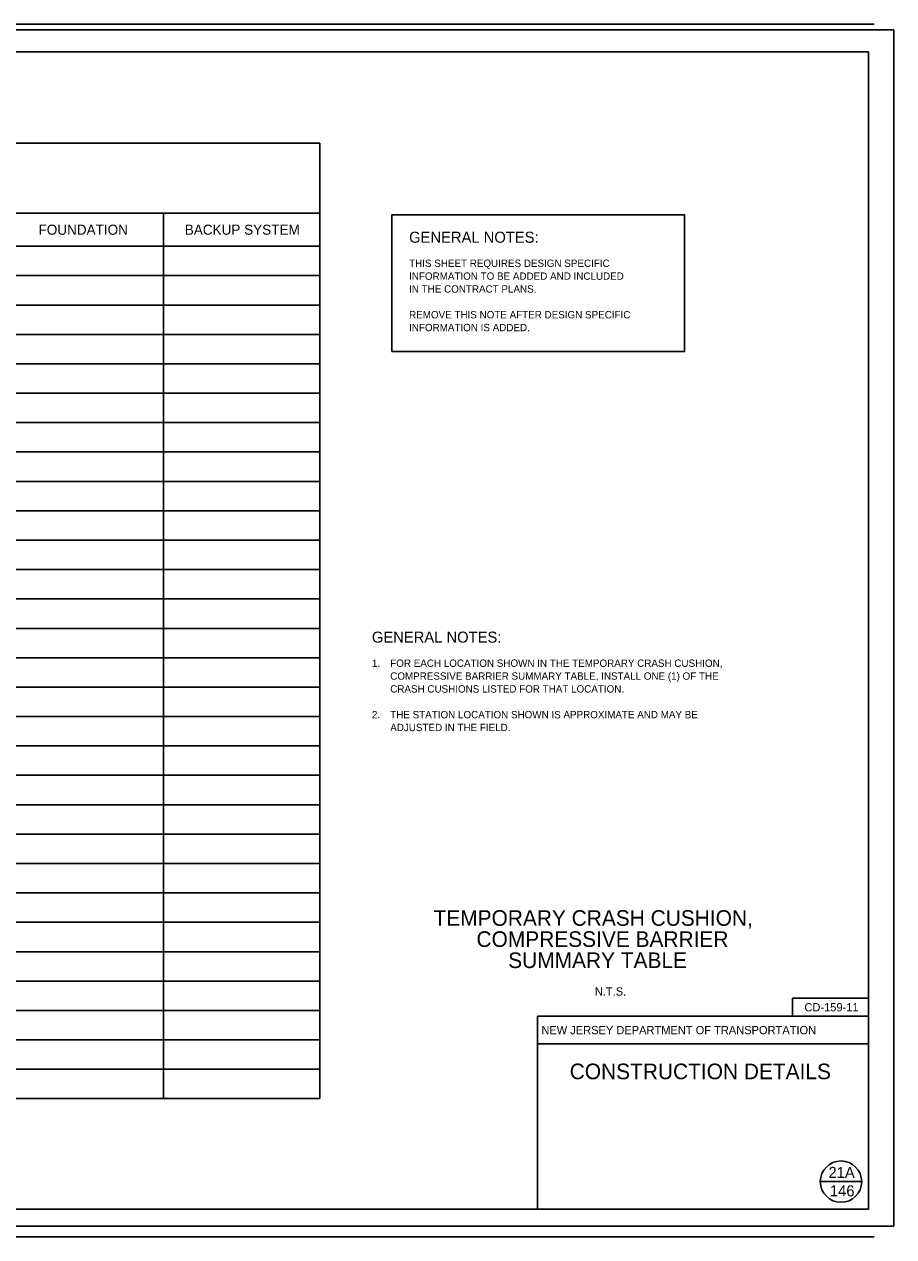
# Model space of a CAD drawing. Extents: x 465470 to 466531, y 459205 to 459865.
# Drawn here: x 466058 to 466531, y 459205 to 459865 of the extents above; entities that cross this region are included whole.
import ezdxf

# ---------------------------------------------------------------- set-up
doc = ezdxf.new("R2010")
doc.units = 0
for name, color, linetype in [('1', 7, 'Continuous'), ('41', 7, 'Continuous'), ('5', 7, 'Continuous'), ('63', 7, 'Continuous')]:
    doc.layers.add(name, color=color, linetype=linetype)

msp = doc.modelspace()

# ---------------------------------------------------------------- linework, layer by layer
at = {"layer": '1'}
for p, q in [((466520.35, 459865.34), (465472.17, 459865.34)), ((466517.35, 459850.34), (465527.35, 459850.34)), ((466517.35, 459220.34), (466517.35, 459850.34)), ((465558.8, 459800.64), (466218.8, 459800.64)), ((466218.8, 459280.52), (466218.8, 459800.64)), ((465558.8, 459762.52), (466218.8, 459762.52)), ((466133.8, 459280.52), (466133.8, 459762.52)), ((465558.8, 459744.52), (466218.8, 459744.52)), ((465558.8, 459728.52), (466218.8, 459728.52)), ((465558.8, 459712.52), (466218.8, 459712.52)), ((465558.8, 459696.52), (466218.8, 459696.52)), ((465558.8, 459680.52), (466218.8, 459680.52)), ((465558.8, 459664.52), (466218.8, 459664.52)), ((465558.8, 459648.52), (466218.8, 459648.52)), ((465558.8, 459632.52), (466218.8, 459632.52)), ((465558.8, 459616.52), (466218.8, 459616.52)), ((465558.8, 459600.52), (466218.8, 459600.52)), ((465558.8, 459584.52), (466218.8, 459584.52)), ((465558.8, 459568.52), (466218.8, 459568.52)), ((465558.8, 459552.52), (466218.8, 459552.52)), ((465558.8, 459536.52), (466218.8, 459536.52)), ((465558.8, 459520.52), (466218.8, 459520.52)), ((465558.8, 459504.52), (466218.8, 459504.52)), ((465558.8, 459488.52), (466218.8, 459488.52)), ((465558.8, 459472.52), (466218.8, 459472.52)), ((465558.8, 459456.52), (466218.8, 459456.52)), ((465558.8, 459440.52), (466218.8, 459440.52)), ((465558.8, 459424.52), (466218.8, 459424.52)), ((465558.8, 459408.52), (466218.8, 459408.52)), ((465558.8, 459392.52), (466218.8, 459392.52)), ((465558.8, 459376.52), (466218.8, 459376.52)), ((465558.8, 459360.52), (466218.8, 459360.52)), ((465558.8, 459344.52), (466218.8, 459344.52)), ((466517.35, 459335.19), (466476.01, 459335.19)), ((466476.01, 459335.19), (466476.01, 459325.34)), ((465558.8, 459328.52), (466218.8, 459328.52)), ((466517.35, 459325.34), (466337.35, 459325.34)), ((466337.35, 459325.34), (466337.35, 459220.34)), ((465558.8, 459312.52), (466218.8, 459312.52)), ((466517.35, 459310.34), (466337.35, 459310.34)), ((465558.8, 459296.52), (466218.8, 459296.52)), ((465558.8, 459280.52), (466218.8, 459280.52)), ((466502.35, 459235.34), (466491.1, 459235.34)), ((466502.35, 459235.34), (466513.6, 459235.34)), ((465527.35, 459220.34), (466517.35, 459220.34)), ((466520.35, 459205.34), (465472.17, 459205.34))]:
    msp.add_line(p, q, dxfattribs=at)
msp.add_lwpolyline([(466258.02, 459687.2), (466417.29, 459687.2), (466417.29, 459761.57), (466258.02, 459761.57)], close=True, dxfattribs=at)
msp.add_circle((466502.35, 459235.34), 11.25, dxfattribs=at)
at = {"layer": '41'}
msp.add_line((466496.68, 459330.27), (466496.68, 459330.27), dxfattribs=at)
msp.add_lwpolyline([(465469.62, 459211.1), (466531.03, 459211.1), (466531.03, 459862.3), (465469.62, 459862.3)], close=True, dxfattribs=at)

# ---------------------------------------------------------------- texts
at = {"layer": '1'}
for s, height, p in [('THIS SHEET REQUIRES DESIGN SPECIFIC', 4, (466267.43, 459733.25)), ('INFORMATION TO BE ADDED AND INCLUDED', 4, (466267.43, 459726.25)), ('IN THE CONTRACT PLANS. ', 4, (466267.43, 459719.25)), ('REMOVE THIS NOTE AFTER DESIGN SPECIFIC', 4, (466267.43, 459705.25)), ('INFORMATION IS ADDED.', 4, (466267.43, 459698.25)), ('TEMPORARY CRASH CUSHION,', 8.5, (466280.71, 459374.61)), ('COMPRESSIVE BARRIER', 8.5, (466304.08, 459363.11)), ('SUMMARY TABLE', 8.5, (466321.33, 459351.61)), ('CD-159-11', 4.5, (466482.46, 459328.02)), ('NEW JERSEY DEPARTMENT OF TRANSPORTATION', 4.5, (466339.37, 459315.59)), ('CONSTRUCTION DETAILS', 8.5, (466354.79, 459291.09)), ('146', 6, (466496.32, 459227.34))]:
    msp.add_text(s, height=height, dxfattribs=at).set_placement(p)
at = {"layer": '5'}
for s, height, p in [('FOUNDATION', 5.5, (466065.86, 459750.77)), ('BACKUP SYSTEM', 5.5, (466145.42, 459750.77)), ('GENERAL NOTES:', 6, (466267.43, 459746.42)), ('GENERAL NOTES:', 6, (466247.19, 459528.73)), ('1.', 4, (466247.19, 459515.55)), ('FOR EACH LOCATION SHOWN IN THE TEMPORARY CRASH CUSHION,', 4, (466257.17, 459515.55)), ('COMPRESSIVE BARRIER SUMMARY TABLE, INSTALL ONE (1) OF THE', 4, (466257.17, 459508.55)), ('CRASH CUSHIONS LISTED FOR THAT LOCATION.', 4, (466257.17, 459501.55)), ('2.', 4, (466247.19, 459487.55)), ('THE STATION LOCATION SHOWN IS APPROXIMATE AND MAY BE', 4, (466257.17, 459487.55)), ('ADJUSTED IN THE FIELD.', 4, (466257.17, 459480.55)), ('N.T.S.', 4.5, (466368.45, 459336.61))]:
    msp.add_text(s, height=height, dxfattribs=at).set_placement(p)
at = {"layer": '63'}
msp.add_text('21A', height=6, dxfattribs=at).set_placement((466495.55, 459237.34))

doc.saveas('drawing.dxf')
